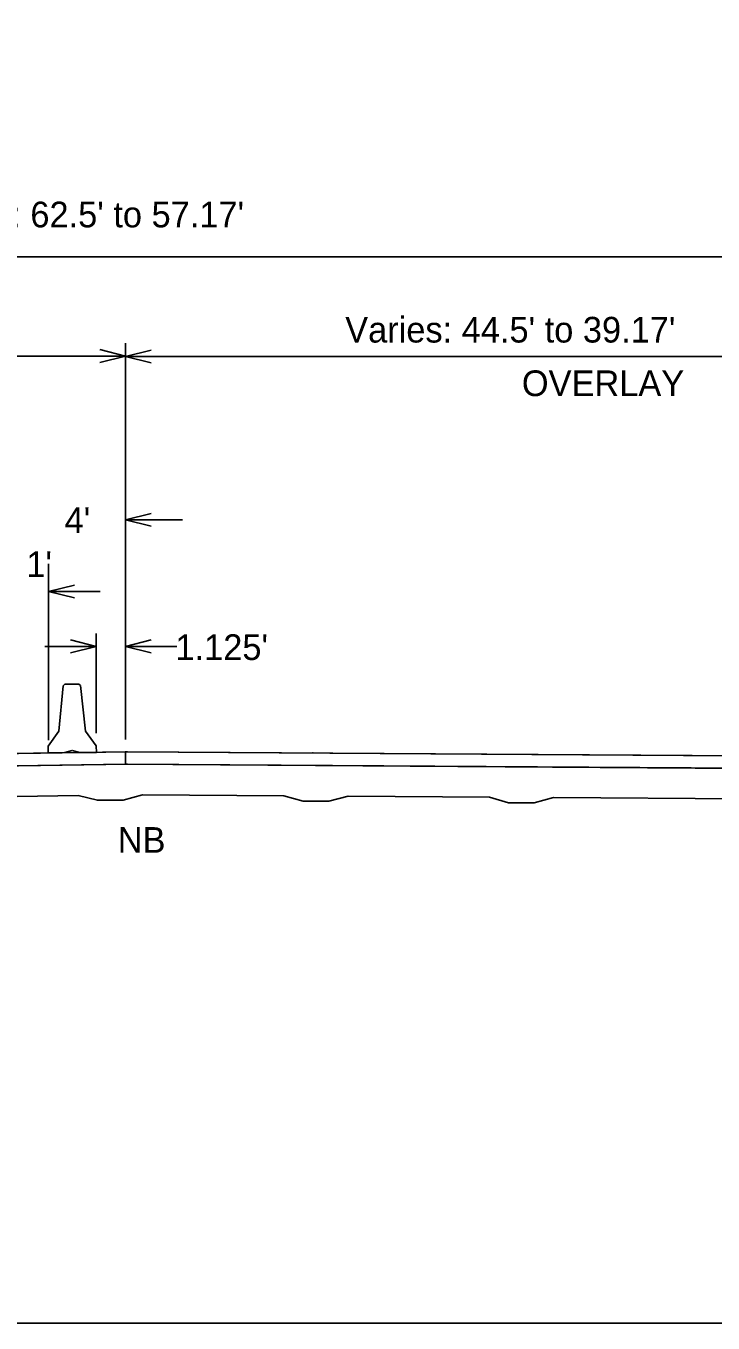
# Model space of a CAD drawing. Extents: x 10133 to 81668, y 7924 to 11018.
# Drawn here: x 12159 to 12694, y 7924 to 8934 of the extents above; entities that cross this region are included whole.
import ezdxf

# ---------------------------------------------------------------- set-up
doc = ezdxf.new("R2010")
doc.units = 0
for name, color, linetype in [('brgConcrete', 7, 'Continuous'), ('brgConstructionLines', 7, 'Continuous'), ('brgPreStructureExisting', 7, 'Continuous'), ('dsnStdLineDrawingWt2', 7, 'Continuous'), ('dsnTextCpn', 7, 'Continuous'), ('SheetBorder', 7, 'Continuous')]:
    doc.layers.add(name, color=color, linetype=linetype)

msp = doc.modelspace()

# ---------------------------------------------------------------- linework, layer by layer
at = {"layer": 'brgConcrete'}
for p, q in [((12236.4, 8368.9), (12238.1, 8368.9)), ((12236.4, 8368.9), (12236.4, 8359.1)), ((12907, 8364.5), (12238.1, 8368.9)), ((12236.4, 8359.1), (12238.1, 8359.2)), ((12907.1, 8354.7), (12236.4, 8359.1)), ((12907, 8354.7), (12238.1, 8359.2))]:
    msp.add_line(p, q, dxfattribs=at)
at = {"layer": 'brgConstructionLines'}
msp.add_circle((12382.3, 8368.1), 0.104, dxfattribs=at)
at = {"layer": 'brgPreStructureExisting'}
for p, q in [((11877.8, 8363.5), (12238.1, 8368.9)), ((12677.5, 8366), (12238.1, 8368.9)), ((11877.8, 8353.7), (12238.1, 8359.2)), ((12089.7, 8333.2), (12199.7, 8334.8)), ((12359.7, 8334.6), (12249.7, 8335.3)), ((12519.7, 8333.5), (12409.7, 8334.3)), ((12940.4, 8330.7), (12569.7, 8333.2))]:
    msp.add_line(p, q, dxfattribs=at)
for points in [[(12176.4, 8368.1), (12189.3, 8368.2), (12195.1, 8369.9), (12200.9, 8368.3), (12213.9, 8368.4), (12213.8, 8373.4), (12205.4, 8385), (12201.6, 8420.4), (12200.2, 8421.6), (12189.3, 8421.6), (12188, 8420.3), (12184.6, 8384.9), (12176.3, 8373.1)], [(12907, 8364.5), (12907, 8354.7), (12236.4, 8359.1), (12236.4, 8363.7), (12236.4, 8368.9), (12238.1, 8368.9)]]:
    msp.add_lwpolyline(points, close=True, dxfattribs=at)
for points in [[(12249.7, 8335.3), (12234.7, 8331.1), (12214.7, 8331.1), (12199.7, 8334.8)], [(12409.7, 8334.3), (12394.7, 8330.3), (12374.7, 8330.3), (12359.7, 8334.6)], [(12569.7, 8333.2), (12554.7, 8329.2), (12534.7, 8329.2), (12519.7, 8333.5)]]:
    msp.add_lwpolyline(points, dxfattribs=at)
at = {"layer": 'dsnStdLineDrawingWt2'}
for p, q in [((11877.3, 8754.2), (12907, 8754.2)), ((12236.4, 8378.4), (12236.4, 8687)), ((11877.6, 8677), (12236.4, 8677)), ((12236.4, 8676.6), (12907, 8676.6)), ((12280.8, 8549.4), (12236.4, 8549.4)), ((12176.7, 8378), (12176.7, 8515.2)), ((12216.7, 8493.7), (12176.7, 8493.7)), ((12176.7, 8378), (12176.7, 8460.9)), ((12213.8, 8383.4), (12213.8, 8460.9)), ((12236.4, 8378.4), (12236.4, 8460.9)), ((12173.8, 8450.9), (12213.8, 8450.9)), ((12276.4, 8450.9), (12236.4, 8450.9))]:
    msp.add_line(p, q, dxfattribs=at)
for points in [[(12216.4, 8682), (12236.4, 8677), (12216.4, 8672)], [(12256.4, 8671.6), (12236.4, 8676.6), (12256.4, 8681.6)], [(12256.4, 8544.4), (12236.4, 8549.4), (12256.4, 8554.4)], [(12196.7, 8488.7), (12176.7, 8493.7), (12196.7, 8498.7)], [(12193.8, 8455.9), (12213.8, 8450.9), (12193.8, 8445.9)], [(12256.4, 8445.9), (12236.4, 8450.9), (12256.4, 8455.9)]]:
    msp.add_lwpolyline(points, dxfattribs=at)
msp.add_lwpolyline([(12236.4, 8368.9), (12236.4, 8359.1), (11877.8, 8353.7), (11877.8, 8363.5)], close=True, dxfattribs=at)
at = {"layer": 'dsnTextCpn'}
msp.add_line((12291.2, 8368.5), (12291.2, 8368.5), dxfattribs=at)
at = {"layer": 'SheetBorder'}
msp.add_lwpolyline([(10132.5, 9944), (13267.5, 9944), (13267.5, 7924), (10132.5, 7924)], close=True, dxfattribs=at)

# ---------------------------------------------------------------- texts
at = {"layer": 'dsnStdLineDrawingWt2'}
for s, p in [("Varies: 62.5' to 57.17'", (12071.8, 8777.2)), ("Varies: 44.5' to 39.17'", (12407.5, 8687.5)), ('OVERLAY', (12545, 8645.8)), ("4'", (12189.1, 8539.2)), ("1'", (12159.3, 8504.9)), ("1.125'", (12275.4, 8440.3)), ('NB', (12230.5, 8290.2))]:
    msp.add_text(s, height=20, dxfattribs=at).set_placement(p)

doc.saveas('drawing.dxf')
